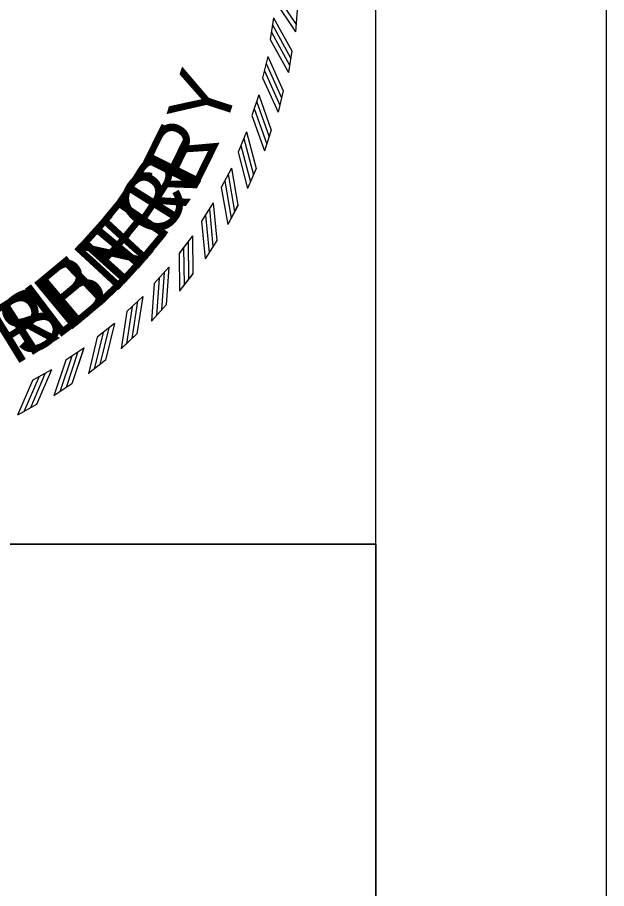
# Model space of a CAD drawing. Extents: x 0 to 1228740, y 0 to 152440.
# Drawn here: x 32.527 to 34, y 16.545 to 18.721 of the extents above; entities that cross this region are included whole.
import ezdxf

# ---------------------------------------------------------------- set-up
doc = ezdxf.new("R2010")
doc.units = 0
for name, color, linetype in [('R_Border', 7, 'Continuous'), ('R_No Plot', 7, 'Continuous'), ('STAMP_Byron', 7, 'Continuous'), ('STAMP_Landon', 7, 'Continuous'), ('STAMP_Scott', 7, 'Continuous')]:
    doc.layers.add(name, color=color, linetype=linetype)

msp = doc.modelspace()

# ---------------------------------------------------------------- linework, layer by layer
at = {"layer": 'R_Border'}
msp.add_line((33.4231, 0.5768), (33.4231, 21.4232), dxfattribs=at)
msp.add_lwpolyline([(33.9999, 22), (0, 22), (0, 0), (33.9999, 0)], close=True, dxfattribs=at)
at = {"layer": 'R_No Plot'}
for points in [[(33.4231, 17.4052), (33.4231, 10.8708), (1.516, 10.8708), (1.516, 21.4232), (25.1971, 21.4232), (25.1971, 20.4352), (28.7491, 20.4352), (28.7491, 20.0782), (29.1131, 20.0782), (29.1131, 20.1432), (30.6665, 20.1432)], [(30.6665, 20.1432), (29.1131, 20.1432), (29.1131, 20.0782), (28.7491, 20.0782), (28.7491, 20.4352), (25.1971, 20.4352), (25.1971, 21.4232), (1.516, 21.4232), (1.516, 0.5768), (33.4231, 0.5768), (33.4231, 17.4052)], [(30.6665, 20.1432), (30.6665, 17.4052), (33.4231, 17.4052)], [(33.4231, 17.4052), (30.6665, 17.4052), (30.6665, 20.1432)]]:
    msp.add_lwpolyline(points, dxfattribs=at)
at = {"layer": 'STAMP_Byron'}
for p, q in [((33.2265, 18.7396), (33.2225, 18.6853)), ((33.2265, 18.7396), (33.2225, 18.6853)), ((33.1676, 18.7202), (33.1591, 18.6664)), ((33.1676, 18.7202), (33.1591, 18.6664)), ((33.2133, 18.6379), (33.2048, 18.5842)), ((33.2133, 18.6379), (33.2048, 18.5842)), ((33.153, 18.6235), (33.1401, 18.5705)), ((33.153, 18.6235), (33.1401, 18.5705)), ((33.1305, 18.5282), (33.1132, 18.4765)), ((33.1305, 18.5282), (33.1132, 18.4765)), ((33.1917, 18.5376), (33.1788, 18.4848)), ((33.1917, 18.5376), (33.1788, 18.4848)), ((33.1001, 18.4352), (33.0787, 18.385)), ((33.1001, 18.4352), (33.0787, 18.385)), ((33.1619, 18.4395), (33.1447, 18.3879)), ((33.1619, 18.4395), (33.1447, 18.3879)), ((33.0622, 18.3449), (33.0367, 18.2967)), ((33.0622, 18.3449), (33.0367, 18.2967)), ((33.1242, 18.3441), (33.1028, 18.2941)), ((33.1242, 18.3441), (33.1028, 18.2941)), ((33.017, 18.2581), (32.9876, 18.2122)), ((33.017, 18.2581), (32.9876, 18.2122)), ((33.0787, 18.2522), (33.0532, 18.2041)), ((33.0787, 18.2522), (33.0532, 18.2041)), ((32.9647, 18.1754), (32.9316, 18.132)), ((32.9647, 18.1754), (32.9316, 18.132)), ((33.0257, 18.1644), (32.9964, 18.1186)), ((33.0257, 18.1644), (32.9964, 18.1186)), ((32.9058, 18.0972), (32.8693, 18.0568)), ((32.9058, 18.0972), (32.8693, 18.0568)), ((32.9657, 18.0812), (32.9327, 18.038)), ((32.9657, 18.0812), (32.9327, 18.038)), ((32.8407, 18.0242), (32.8009, 17.9869)), ((32.8407, 18.0242), (32.8009, 17.9869)), ((32.899, 18.0033), (32.8625, 17.9629)), ((32.899, 18.0033), (32.8625, 17.9629)), ((32.7697, 17.9568), (32.727, 17.9229)), ((32.7697, 17.9568), (32.727, 17.9229)), ((32.8261, 17.9312), (32.7864, 17.8939)), ((32.8261, 17.9312), (32.7864, 17.8939)), ((32.6934, 17.8955), (32.648, 17.8652)), ((32.6934, 17.8955), (32.648, 17.8652)), ((32.7475, 17.8653), (32.7049, 17.8315)), ((32.7475, 17.8653), (32.7049, 17.8315)), ((32.6123, 17.8407), (32.5646, 17.8143)), ((32.6123, 17.8407), (32.5646, 17.8143)), ((32.6637, 17.8061), (32.6185, 17.7759)), ((32.6637, 17.8061), (32.6185, 17.7759)), ((32.5754, 17.7541), (32.5278, 17.7277)), ((32.5754, 17.7541), (32.5278, 17.7277))]:
    msp.add_line(p, q, dxfattribs=at)
for points in [[(33.1717, 18.7816), (33.224, 18.7034)], [(33.1717, 18.7816), (33.224, 18.7034)], [(33.1702, 18.7636), (33.2225, 18.6853)], [(33.1702, 18.7636), (33.2225, 18.6853)], [(33.1676, 18.7203), (33.2132, 18.638)], [(33.1676, 18.7203), (33.2132, 18.638)], [(33.1647, 18.703), (33.2103, 18.6207)], [(33.1647, 18.703), (33.2103, 18.6207)], [(33.1622, 18.6843), (33.2078, 18.602)], [(33.1622, 18.6843), (33.2078, 18.602)], [(33.1592, 18.6664), (33.2048, 18.5841)], [(33.1592, 18.6664), (33.2048, 18.5841)], [(33.1487, 18.6066), (33.1874, 18.5207)], [(33.1487, 18.6066), (33.1874, 18.5207)], [(33.153, 18.6235), (33.1917, 18.5377)], [(33.153, 18.6235), (33.1917, 18.5377)], [(33.1446, 18.5881), (33.1833, 18.5023)], [(33.1446, 18.5881), (33.1833, 18.5023)], [(33.1402, 18.5705), (33.1789, 18.4847)], [(33.1402, 18.5705), (33.1789, 18.4847)], [(33.1304, 18.5283), (33.1619, 18.4396)], [(33.1304, 18.5283), (33.1619, 18.4396)], [(33.1247, 18.5117), (33.1562, 18.423)], [(33.1247, 18.5117), (33.1562, 18.423)], [(33.1133, 18.4765), (33.1448, 18.3878)], [(33.1133, 18.4765), (33.1448, 18.3878)], [(33.1192, 18.4937), (33.1506, 18.405)], [(33.1192, 18.4937), (33.1506, 18.405)], [(33.1001, 18.4352), (33.1241, 18.3442)], [(33.1001, 18.4352), (33.1241, 18.3442)], [(33.0931, 18.4192), (33.1171, 18.3282)], [(33.0931, 18.4192), (33.1171, 18.3282)], [(33.086, 18.4017), (33.1101, 18.3107)], [(33.086, 18.4017), (33.1101, 18.3107)], [(33.0787, 18.3851), (33.1028, 18.2941)], [(33.0787, 18.3851), (33.1028, 18.2941)], [(33.0622, 18.345), (33.0786, 18.2523)], [(33.0622, 18.345), (33.0786, 18.2523)], [(33.0539, 18.3296), (33.0703, 18.2369)], [(33.0539, 18.3296), (33.0703, 18.2369)], [(33.0454, 18.3127), (33.0618, 18.22)], [(33.0454, 18.3127), (33.0618, 18.22)], [(33.0368, 18.2968), (33.0532, 18.2041)], [(33.0368, 18.2968), (33.0532, 18.2041)], [(33.017, 18.2582), (33.0257, 18.1645)], [(33.017, 18.2582), (33.0257, 18.1645)], [(33.0074, 18.2436), (33.0161, 18.1498)], [(33.0074, 18.2436), (33.0161, 18.1498)], [(32.9976, 18.2274), (33.0063, 18.1337)], [(32.9976, 18.2274), (33.0063, 18.1337)], [(32.9876, 18.2122), (32.9964, 18.1185)], [(32.9876, 18.2122), (32.9964, 18.1185)], [(32.9647, 18.1755), (32.9657, 18.0813)], [(32.9647, 18.1755), (32.9657, 18.0813)], [(32.954, 18.1616), (32.9549, 18.0675)], [(32.954, 18.1616), (32.9549, 18.0675)], [(32.9317, 18.1321), (32.9327, 18.0379)], [(32.9317, 18.1321), (32.9327, 18.0379)], [(32.9428, 18.1464), (32.9438, 18.0522)], [(32.9428, 18.1464), (32.9438, 18.0522)], [(32.894, 18.0844), (32.8872, 17.9905)], [(32.894, 18.0844), (32.8872, 17.9905)], [(32.9058, 18.0973), (32.899, 18.0034)], [(32.9058, 18.0973), (32.899, 18.0034)], [(32.8816, 18.0701), (32.8748, 17.9762)], [(32.8816, 18.0701), (32.8748, 17.9762)], [(32.8693, 18.0568), (32.8625, 17.9629)], [(32.8693, 18.0568), (32.8625, 17.9629)], [(32.8407, 18.0243), (32.8261, 17.9313)], [(32.8407, 18.0243), (32.8261, 17.9313)], [(32.8143, 17.9992), (32.7997, 17.9062)], [(32.8143, 17.9992), (32.7997, 17.9062)], [(32.8278, 18.0124), (32.8132, 17.9194)], [(32.8278, 18.0124), (32.8132, 17.9194)], [(32.801, 17.9869), (32.7864, 17.8939)], [(32.801, 17.9869), (32.7864, 17.8939)], [(32.7697, 17.9569), (32.7475, 17.8654)], [(32.7697, 17.9569), (32.7475, 17.8654)], [(32.7414, 17.934), (32.7192, 17.8425)], [(32.7414, 17.934), (32.7192, 17.8425)], [(32.7559, 17.9461), (32.7337, 17.8546)], [(32.7559, 17.9461), (32.7337, 17.8546)], [(32.7271, 17.9229), (32.7049, 17.8314)], [(32.7271, 17.9229), (32.7049, 17.8314)], [(32.6934, 17.8955), (32.6638, 17.8062)], [(32.6934, 17.8955), (32.6638, 17.8062)], [(32.6481, 17.8652), (32.6184, 17.7759)], [(32.6481, 17.8652), (32.6184, 17.7759)], [(32.6633, 17.8751), (32.6336, 17.7858)], [(32.6633, 17.8751), (32.6336, 17.7858)], [(32.6788, 17.886), (32.6491, 17.7966)], [(32.6788, 17.886), (32.6491, 17.7966)], [(32.5806, 17.8229), (32.5437, 17.7363)], [(32.5806, 17.8229), (32.5437, 17.7363)], [(32.5969, 17.8324), (32.56, 17.7458)], [(32.5969, 17.8324), (32.56, 17.7458)], [(32.6124, 17.8407), (32.5754, 17.7541)], [(32.6124, 17.8407), (32.5754, 17.7541)], [(32.5647, 17.8143), (32.5277, 17.7277)], [(32.5647, 17.8143), (32.5277, 17.7277)]]:
    msp.add_lwpolyline(points, dxfattribs=at)
at = {"layer": 'STAMP_Landon'}
for p, q in [((33.2264, 18.7396), (33.2224, 18.6854)), ((33.1676, 18.7203), (33.1591, 18.6664)), ((33.2132, 18.6379), (33.2048, 18.5842)), ((33.153, 18.6235), (33.1401, 18.5705)), ((33.1304, 18.5282), (33.1132, 18.4765)), ((33.1917, 18.5377), (33.1788, 18.4848)), ((33.1001, 18.4352), (33.0787, 18.385)), ((33.1619, 18.4395), (33.1447, 18.3879)), ((33.0622, 18.345), (33.0367, 18.2968)), ((33.1241, 18.3442), (33.1028, 18.2941)), ((33.017, 18.2582), (32.9876, 18.2122)), ((33.0786, 18.2522), (33.0532, 18.2042)), ((32.9647, 18.1754), (32.9316, 18.1321)), ((33.0257, 18.1644), (32.9964, 18.1186)), ((32.9058, 18.0972), (32.8692, 18.0568)), ((32.9657, 18.0813), (32.9326, 18.038)), ((32.8407, 18.0242), (32.8009, 17.9869)), ((32.899, 18.0033), (32.8625, 17.963)), ((32.7697, 17.9568), (32.727, 17.9229)), ((32.8261, 17.9312), (32.7864, 17.894)), ((32.6934, 17.8955), (32.648, 17.8652)), ((32.7475, 17.8653), (32.7049, 17.8315)), ((32.6123, 17.8407), (32.5646, 17.8143)), ((32.6637, 17.8061), (32.6185, 17.776)), ((32.5754, 17.7541), (32.5278, 17.7278))]:
    msp.add_line(p, q, dxfattribs=at)
for points in [[(33.1717, 18.7817), (33.224, 18.7034)], [(33.1702, 18.7636), (33.2225, 18.6853)], [(33.1676, 18.7203), (33.2132, 18.638)], [(33.1647, 18.7031), (33.2103, 18.6207)], [(33.1621, 18.6843), (33.2078, 18.602)], [(33.1592, 18.6664), (33.2048, 18.5841)], [(33.1487, 18.6066), (33.1873, 18.5208)], [(33.153, 18.6236), (33.1916, 18.5377)], [(33.1446, 18.5881), (33.1833, 18.5023)], [(33.1401, 18.5706), (33.1788, 18.4847)], [(33.1304, 18.5283), (33.1619, 18.4396)], [(33.1247, 18.5118), (33.1562, 18.423)], [(33.1133, 18.4766), (33.1447, 18.3878)], [(33.1192, 18.4937), (33.1506, 18.405)], [(33.1001, 18.4353), (33.1241, 18.3442)], [(33.0931, 18.4192), (33.1171, 18.3282)], [(33.086, 18.4017), (33.11, 18.3107)], [(33.0787, 18.3851), (33.1028, 18.2941)], [(33.0622, 18.345), (33.0786, 18.2523)], [(33.0539, 18.3296), (33.0703, 18.2369)], [(33.0454, 18.3127), (33.0618, 18.22)], [(33.0368, 18.2968), (33.0532, 18.2041)], [(33.017, 18.2582), (33.0257, 18.1645)], [(33.0074, 18.2436), (33.0161, 18.1498)], [(32.9975, 18.2274), (33.0063, 18.1337)], [(32.9876, 18.2123), (32.9964, 18.1185)], [(32.9647, 18.1755), (32.9657, 18.0813)], [(32.954, 18.1617), (32.9549, 18.0675)], [(32.9317, 18.1321), (32.9326, 18.0379)], [(32.9428, 18.1464), (32.9438, 18.0523)], [(32.894, 18.0844), (32.8871, 17.9905)], [(32.9058, 18.0973), (32.899, 18.0034)], [(32.8816, 18.0701), (32.8748, 17.9762)], [(32.8693, 18.0568), (32.8625, 17.9629)], [(32.8407, 18.0243), (32.8261, 17.9313)], [(32.8143, 17.9992), (32.7997, 17.9062)], [(32.8278, 18.0124), (32.8132, 17.9194)], [(32.8009, 17.9869), (32.7864, 17.8939)], [(32.7697, 17.9569), (32.7475, 17.8654)], [(32.7413, 17.9341), (32.7192, 17.8426)], [(32.7559, 17.9461), (32.7337, 17.8546)], [(32.727, 17.9229), (32.7049, 17.8314)], [(32.6934, 17.8956), (32.6638, 17.8062)], [(32.6481, 17.8652), (32.6184, 17.7759)], [(32.6633, 17.8752), (32.6336, 17.7858)], [(32.6788, 17.886), (32.6491, 17.7966)], [(32.5806, 17.8229), (32.5437, 17.7363)], [(32.5969, 17.8324), (32.56, 17.7458)], [(32.6123, 17.8408), (32.5754, 17.7542)], [(32.5647, 17.8143), (32.5277, 17.7277)]]:
    msp.add_lwpolyline(points, dxfattribs=at)
at = {"layer": 'STAMP_Scott'}
for p, q in [((33.2265, 18.7396), (33.2225, 18.6853)), ((33.1676, 18.7202), (33.1591, 18.6664)), ((33.2133, 18.6379), (33.2048, 18.5842)), ((33.153, 18.6235), (33.1401, 18.5705)), ((33.1305, 18.5282), (33.1132, 18.4765)), ((33.1917, 18.5376), (33.1788, 18.4848)), ((33.1001, 18.4352), (33.0787, 18.385)), ((33.1619, 18.4395), (33.1447, 18.3879)), ((33.0622, 18.3449), (33.0367, 18.2967)), ((33.1242, 18.3441), (33.1028, 18.2941)), ((33.017, 18.2581), (32.9876, 18.2122)), ((33.0787, 18.2522), (33.0532, 18.2041)), ((32.9647, 18.1754), (32.9316, 18.132)), ((33.0257, 18.1644), (32.9964, 18.1186)), ((32.9058, 18.0972), (32.8693, 18.0568)), ((32.9657, 18.0812), (32.9327, 18.038)), ((32.8407, 18.0242), (32.8009, 17.9869)), ((32.899, 18.0033), (32.8625, 17.9629)), ((32.7697, 17.9568), (32.727, 17.9229)), ((32.8261, 17.9312), (32.7864, 17.8939)), ((32.6934, 17.8955), (32.648, 17.8652)), ((32.7475, 17.8653), (32.7049, 17.8315)), ((32.6123, 17.8407), (32.5646, 17.8143)), ((32.6637, 17.8061), (32.6185, 17.7759)), ((32.5754, 17.7541), (32.5278, 17.7277))]:
    msp.add_line(p, q, dxfattribs=at)
for points in [[(33.1717, 18.7816), (33.224, 18.7034)], [(33.1702, 18.7636), (33.2225, 18.6853)], [(33.1676, 18.7203), (33.2132, 18.638)], [(33.1647, 18.703), (33.2103, 18.6207)], [(33.1622, 18.6843), (33.2078, 18.602)], [(33.1592, 18.6664), (33.2048, 18.5841)], [(33.1487, 18.6066), (33.1874, 18.5207)], [(33.153, 18.6235), (33.1917, 18.5377)], [(33.1446, 18.5881), (33.1833, 18.5023)], [(33.1402, 18.5705), (33.1789, 18.4847)], [(33.1304, 18.5283), (33.1619, 18.4396)], [(33.1247, 18.5117), (33.1562, 18.423)], [(33.1133, 18.4765), (33.1448, 18.3878)], [(33.1192, 18.4937), (33.1506, 18.405)], [(33.1001, 18.4352), (33.1241, 18.3442)], [(33.0931, 18.4192), (33.1171, 18.3282)], [(33.086, 18.4017), (33.1101, 18.3107)], [(33.0787, 18.3851), (33.1028, 18.2941)], [(33.0622, 18.345), (33.0786, 18.2523)], [(33.0539, 18.3296), (33.0703, 18.2369)], [(33.0454, 18.3127), (33.0618, 18.22)], [(33.0368, 18.2968), (33.0532, 18.2041)], [(33.017, 18.2582), (33.0257, 18.1645)], [(33.0074, 18.2436), (33.0161, 18.1498)], [(32.9976, 18.2274), (33.0063, 18.1337)], [(32.9876, 18.2122), (32.9964, 18.1185)], [(32.9647, 18.1755), (32.9657, 18.0813)], [(32.954, 18.1616), (32.9549, 18.0675)], [(32.9317, 18.1321), (32.9327, 18.0379)], [(32.9428, 18.1464), (32.9438, 18.0522)], [(32.894, 18.0844), (32.8872, 17.9905)], [(32.9058, 18.0973), (32.899, 18.0034)], [(32.8816, 18.0701), (32.8748, 17.9762)], [(32.8693, 18.0568), (32.8625, 17.9629)], [(32.8407, 18.0243), (32.8261, 17.9313)], [(32.8143, 17.9992), (32.7997, 17.9062)], [(32.8278, 18.0124), (32.8132, 17.9194)], [(32.801, 17.9869), (32.7864, 17.8939)], [(32.7697, 17.9569), (32.7475, 17.8654)], [(32.7414, 17.934), (32.7192, 17.8425)], [(32.7559, 17.9461), (32.7337, 17.8546)], [(32.7271, 17.9229), (32.7049, 17.8314)], [(32.6934, 17.8955), (32.6638, 17.8062)], [(32.6481, 17.8652), (32.6184, 17.7759)], [(32.6633, 17.8751), (32.6336, 17.7858)], [(32.6788, 17.886), (32.6491, 17.7966)], [(32.5806, 17.8229), (32.5437, 17.7363)], [(32.5969, 17.8324), (32.56, 17.7458)], [(32.6124, 17.8407), (32.5754, 17.7541)], [(32.5647, 17.8143), (32.5277, 17.7277)]]:
    msp.add_lwpolyline(points, dxfattribs=at)

# ---------------------------------------------------------------- texts
at = {"layer": 'STAMP_Byron'}
for s, rotation, p in [('E', 63.7362, (32.9691, 18.2801)), ('E', 63.7362, (32.9691, 18.2801)), ('C', 56.0754, (32.8846, 18.1554)), ('C', 56.0754, (32.8846, 18.1554)), ('N', 47.3202, (32.7688, 18.0282)), ('N', 47.3202, (32.7688, 18.0282)), ('E', 39.6594, (32.6526, 17.9324)), ('E', 39.6594, (32.6526, 17.9324)), ('R', 31.6338, (32.5183, 17.8497)), ('R', 31.6338, (32.5183, 17.8497))]:
    msp.add_text(s, height=0.1503, rotation=rotation, dxfattribs=at).set_placement(p)
at = {"layer": 'STAMP_Landon'}
for s, rotation, p in [('R', 57.9868, (32.9148, 18.1976)), ('E', 50.326, (32.8199, 18.0809)), ('L', 43.7596, (32.7267, 17.9916)), ('L', 37.1932, (32.624, 17.9137)), ('I', 32.8156, (32.5508, 17.8684))]:
    msp.add_text(s, height=0.1503, rotation=rotation, dxfattribs=at).set_placement(p)
at = {"layer": 'STAMP_Scott'}
for s, rotation, p in [('Y', 71.7733, (33.0412, 18.4286)), ('R', 63.7477, (32.9723, 18.2867)), ('R', 55.7221, (32.8844, 18.1558)), ('E', 48.0613, (32.7841, 18.0436)), ('B', 40.0357, (32.6641, 17.9413)), ('S', 32.7397, (32.5435, 17.8638))]:
    msp.add_text(s, height=0.1503, rotation=rotation, dxfattribs=at).set_placement(p)

doc.saveas('drawing.dxf')
